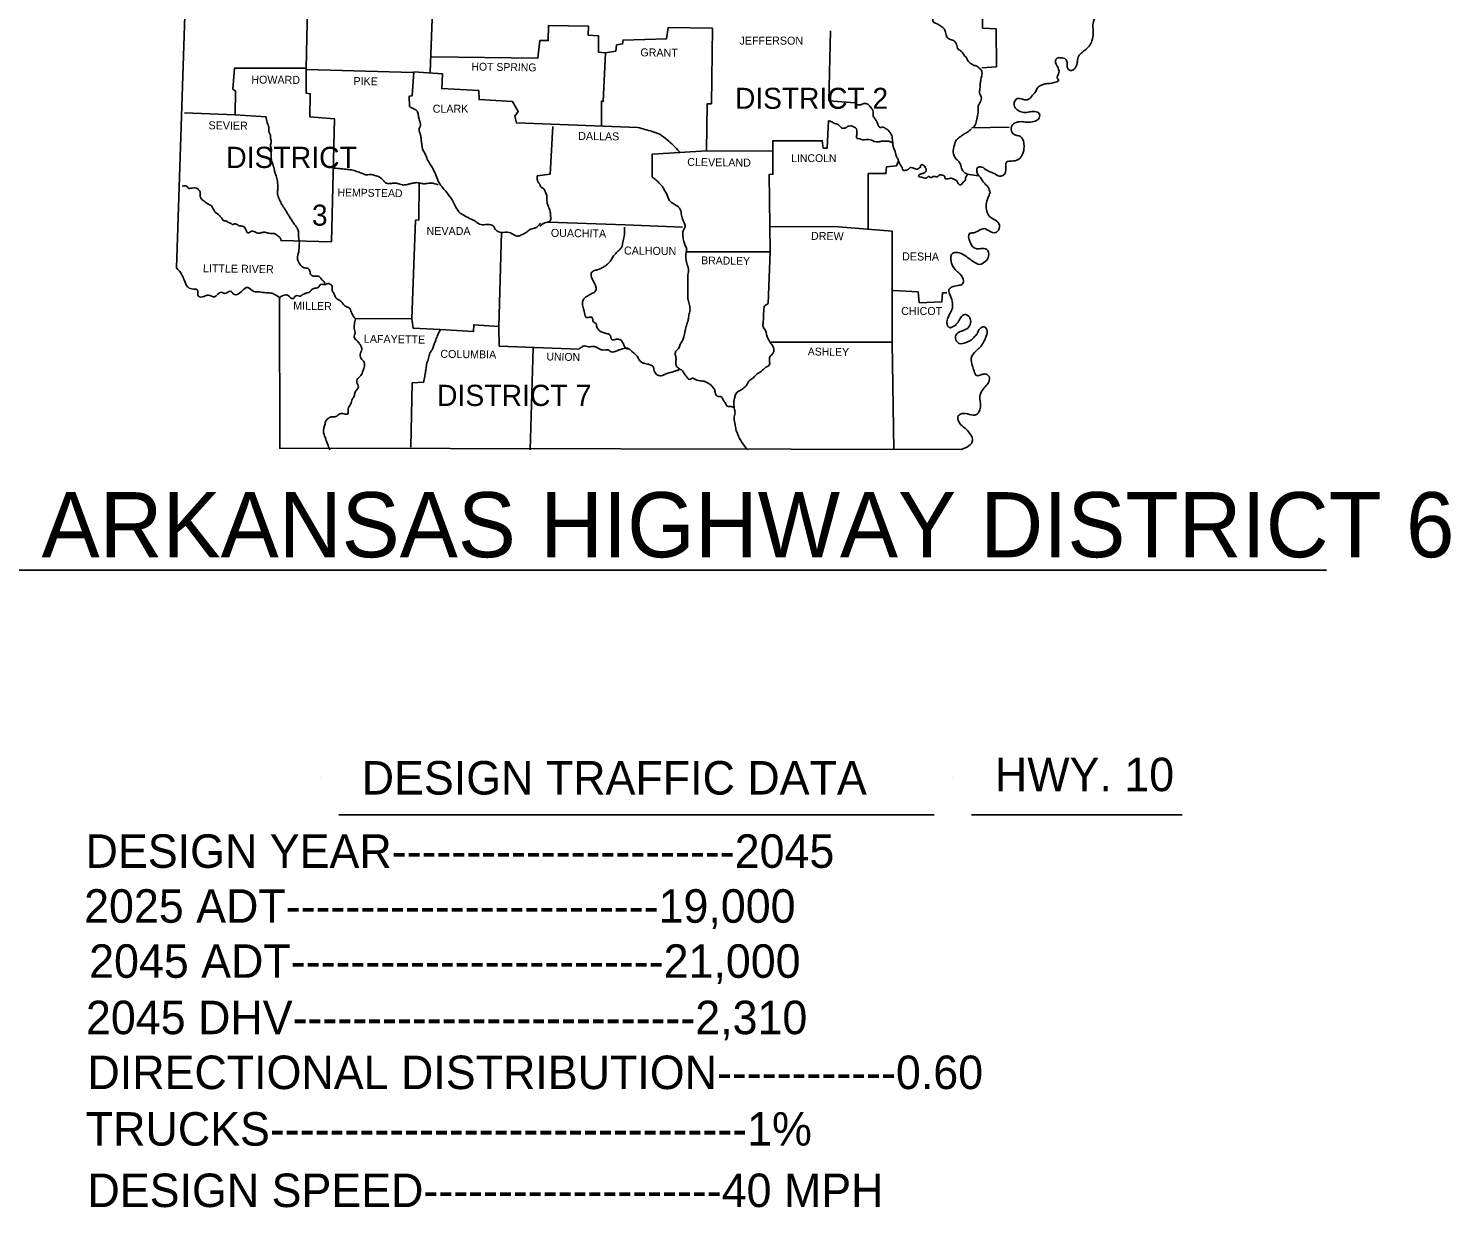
# Model space of a CAD drawing. Extents: x 1096785 to 1382432, y 216169 to 341661.
# Drawn here: x 1204876 to 1220163, y 273845 to 286518 of the extents above; entities that cross this region are included whole.
import ezdxf

# ---------------------------------------------------------------- set-up
doc = ezdxf.new("R2010")
doc.units = 0
for name, color, linetype in [('1', 7, 'Continuous'), ('21', 7, 'Continuous'), ('3', 7, 'Continuous')]:
    doc.layers.add(name, color=color, linetype=linetype)

msp = doc.modelspace()

# ---------------------------------------------------------------- linework, layer by layer
at = {"layer": '1'}
for p, q in [((1215017, 285450), (1215417, 285456)), ((1215089, 284934), (1214963, 284950)), ((1203995, 280696), (1218830, 280696)), ((1208012, 278464), (1208012, 278464)), ((1214812, 278464), (1214812, 278464)), ((1208212, 278064), (1214612, 278064)), ((1215012, 278064), (1217276, 278064))]:
    msp.add_line(p, q, dxfattribs=at)
for points in [[(1206467, 283946), (1206647, 289372), (1206233, 292696)], [(1206553, 285612), (1207099, 285588), (1207101, 285844), (1207073, 285864), (1207091, 286092), (1207861, 286090), (1207883, 287074), (1208019, 287062), (1208021, 287184), (1208161, 287188), (1208159, 287220), (1208253, 287220), (1208255, 287264), (1208351, 287262), (1208343, 287322), (1208443, 287324), (1208446, 288143)], [(1215125, 286096), (1215281, 286106), (1215279, 286512), (1215133, 286522), (1215141, 287316), (1215015, 287334), (1215011, 287868), (1216717, 287880)], [(1209193, 286048), (1209239, 287294)], [(1209207, 286214), (1210351, 286198), (1210373, 286388), (1210463, 286388), (1210465, 286548), (1210897, 286542), (1210893, 286446), (1211005, 286438), (1211005, 286262), (1211077, 286256)], [(1212229, 286520), (1211751, 286528), (1211733, 286406), (1211267, 286392), (1211263, 286352), (1211197, 286340), (1211189, 286272), (1211077, 286256)], [(1212229, 286516), (1212217, 285708), (1212171, 285706), (1212165, 285204)], [(1213497, 286494), (1213481, 285740), (1213759, 285718)], [(1211077, 286256), (1211053, 285732), (1211035, 285738), (1211037, 285466)], [(1207861, 286090), (1207861, 285824), (1207905, 285816), (1207901, 285568), (1208165, 285548), (1208133, 284226), (1207589, 284240)], [(1207865, 286076), (1209009, 286046)], [(1208971, 285680), (1208967, 285790), (1208999, 285792), (1209019, 286050), (1209327, 286030), (1209319, 285872), (1209717, 285850), (1209719, 285754), (1210079, 285732), (1210141, 285624), (1210103, 285576), (1210121, 285502), (1211425, 285454)], [(1207099, 285588), (1207431, 285568)], [(1210513, 285464), (1210483, 284950), (1210345, 284934)], [(1213475, 285526), (1213463, 285232), (1213417, 285232), (1213409, 285310), (1212877, 285310), (1212877, 285198)], [(1211877, 285186), (1211581, 285168), (1211579, 284918)], [(1211873, 285186), (1212165, 285204)], [(1212165, 285204), (1212873, 285200)], [(1212877, 285200), (1212879, 284950), (1212837, 284948), (1212849, 284118)], [(1214229, 285094), (1214205, 285040), (1214099, 285030), (1214093, 284958), (1213903, 284958), (1213901, 284360)], [(1209077, 284858), (1209073, 284460), (1209037, 284456), (1208997, 283402)], [(1210463, 284436), (1211291, 284406), (1211905, 284382)], [(1212843, 284390), (1213585, 284384), (1214161, 284340)], [(1214161, 284340), (1214161, 283144), (1214177, 281994)], [(1209301, 283282), (1209661, 283260), (1209663, 283334), (1209933, 283316), (1209959, 284324)], [(1211945, 284116), (1212849, 284118)], [(1212849, 284118), (1212829, 283562), (1212785, 283534)], [(1214907, 281994), (1207577, 282006), (1207573, 283624)], [(1214171, 283702), (1214439, 283686), (1214451, 283570), (1214693, 283578), (1214703, 283676), (1214749, 283676)], [(1209301, 283282), (1209011, 283298), (1208997, 283402), (1208391, 283396)], [(1210791, 283072), (1209937, 283104), (1209933, 283306)], [(1212849, 283146), (1214161, 283146)], [(1210301, 283086), (1210269, 281988)], [(1208987, 282016), (1209001, 282708), (1209125, 282716)]]:
    msp.add_lwpolyline(points, dxfattribs=at)
for points in [[(1216591, 287396), (1216545, 287338), (1216477, 287374), (1216477, 287422), (1216487, 287472), (1216463, 287504), (1216421, 287490), (1216421, 287428), (1216417, 287368), (1216405, 287282), (1216433, 287256), (1216497, 287248), (1216543, 287236), (1216571, 287190), (1216569, 287134), (1216547, 287080), (1216515, 287036), (1216465, 287020), (1216425, 287046), (1216409, 287098), (1216391, 287144), (1216357, 287178), (1216321, 287140), (1216313, 287070), (1216315, 287010), (1216315, 286928), (1216367, 286874), (1216399, 286812), (1216389, 286756), (1216351, 286690), (1216335, 286632), (1216319, 286554), (1216321, 286468), (1216307, 286384), (1216279, 286328), (1216227, 286282), (1216193, 286252), (1216165, 286222), (1216151, 286162), (1216141, 286120), (1216103, 286070), (1216073, 286066), (1216049, 286086), (1216041, 286120), (1216041, 286154), (1216025, 286188), (1215975, 286202), (1215935, 286200), (1215917, 286172), (1215943, 286094), (1215953, 286044), (1215939, 285976), (1215947, 285968), (1215875, 285930), (1215817, 285924), (1215769, 285910), (1215723, 285880), (1215701, 285836), (1215669, 285800), (1215641, 285766), (1215603, 285750), (1215561, 285758), (1215505, 285764), (1215473, 285724), (1215483, 285666), (1215521, 285632), (1215577, 285616), (1215635, 285620), (1215691, 285626), (1215743, 285598), (1215733, 285544), (1215683, 285518), (1215609, 285510), (1215549, 285516), (1215477, 285500), (1215441, 285454), (1215461, 285384), (1215539, 285356), (1215575, 285290), (1215577, 285228), (1215551, 285146), (1215515, 285108), (1215445, 285092), (1215391, 285082), (1215383, 284990), (1215359, 284944), (1215317, 284930), (1215257, 284960), (1215221, 284974), (1215177, 284994), (1215121, 285028), (1215079, 285022), (1215091, 284934), (1215095, 284930), (1215143, 284864), (1215191, 284812), (1215213, 284750)], [(1216591, 287396), (1216545, 287338), (1216477, 287374), (1216477, 287422), (1216487, 287472), (1216463, 287504), (1216421, 287490), (1216421, 287428), (1216417, 287368), (1216405, 287282), (1216433, 287256), (1216497, 287248), (1216543, 287236), (1216571, 287190), (1216569, 287134), (1216547, 287080), (1216515, 287036), (1216465, 287020), (1216425, 287046), (1216409, 287098), (1216391, 287144), (1216357, 287178), (1216321, 287140), (1216313, 287070), (1216315, 287010), (1216315, 286928), (1216367, 286874), (1216399, 286812), (1216389, 286756), (1216351, 286690), (1216335, 286632), (1216319, 286554), (1216321, 286468), (1216307, 286384), (1216279, 286328), (1216227, 286282), (1216193, 286252), (1216165, 286222), (1216151, 286162), (1216141, 286120), (1216103, 286070), (1216073, 286066), (1216049, 286086), (1216041, 286120), (1216041, 286154), (1216025, 286188), (1215975, 286202), (1215935, 286200), (1215917, 286172), (1215943, 286094), (1215953, 286044), (1215939, 285976), (1215947, 285968), (1215875, 285930), (1215817, 285924), (1215769, 285910), (1215723, 285880), (1215701, 285836), (1215669, 285800), (1215641, 285766), (1215603, 285750), (1215561, 285758), (1215505, 285764), (1215473, 285724), (1215483, 285666), (1215521, 285632), (1215577, 285616), (1215635, 285620), (1215691, 285626), (1215743, 285598), (1215733, 285544), (1215683, 285518), (1215609, 285510), (1215549, 285516), (1215477, 285500), (1215441, 285454), (1215461, 285384), (1215539, 285356), (1215575, 285290), (1215577, 285228), (1215551, 285146), (1215515, 285108), (1215445, 285092), (1215391, 285082), (1215383, 284990), (1215359, 284944), (1215317, 284930), (1215257, 284960), (1215221, 284974), (1215177, 284994), (1215121, 285028), (1215079, 285022), (1215091, 284934), (1215095, 284930), (1215143, 284864), (1215191, 284812), (1215213, 284750)], [(1215027, 285450), (1215053, 285482), (1215071, 285544), (1215079, 285582), (1215085, 285648), (1215087, 285692), (1215107, 285724), (1215117, 285784), (1215099, 285824), (1215103, 285872), (1215107, 285926), (1215115, 285974), (1215125, 286020), (1215125, 286050), (1215099, 286090), (1215059, 286116), (1215027, 286126), (1215007, 286140), (1214979, 286164), (1214951, 286212), (1214935, 286230), (1214903, 286272), (1214871, 286296), (1214851, 286350), (1214819, 286388), (1214775, 286404), (1214743, 286438), (1214731, 286490), (1214711, 286522), (1214683, 286542), (1214637, 286570), (1214603, 286590), (1214593, 286636), (1214573, 286658), (1214525, 286670), (1214519, 286752)], [(1213759, 285718), (1213789, 285698), (1213831, 285700), (1213859, 285712), (1213881, 285710), (1213911, 285692), (1213931, 285668), (1213945, 285650), (1213955, 285622), (1213955, 285596), (1213965, 285560), (1213977, 285546), (1213993, 285520), (1214003, 285496), (1214009, 285480), (1214031, 285454), (1214051, 285456), (1214069, 285454), (1214093, 285440), (1214129, 285412), (1214135, 285404), (1214159, 285352), (1214163, 285320), (1214167, 285278), (1214175, 285238), (1214191, 285194), (1214199, 285164), (1214217, 285122), (1214229, 285094), (1214245, 285058), (1214269, 285018), (1214279, 284994), (1214313, 284996), (1214337, 285006), (1214355, 285022), (1214377, 285020), (1214401, 285012), (1214433, 285006), (1214453, 285018), (1214463, 285026), (1214465, 285044), (1214483, 285054), (1214503, 285040), (1214525, 285008), (1214525, 284988), (1214517, 284976), (1214491, 284960), (1214455, 284948), (1214445, 284934), (1214479, 284918), (1214533, 284914), (1214547, 284926), (1214583, 284916), (1214597, 284926), (1214645, 284924), (1214667, 284940), (1214711, 284938), (1214725, 284928), (1214725, 284910), (1214761, 284902), (1214787, 284908), (1214821, 284898), (1214851, 284882), (1214867, 284860), (1214887, 284836), (1214905, 284842), (1214919, 284860), (1214949, 284892), (1214949, 284912), (1214957, 284926), (1214967, 284946)], [(1207431, 285568), (1207441, 285508), (1207459, 285456), (1207461, 285416), (1207479, 285356), (1207479, 285334), (1207485, 285290), (1207477, 285266), (1207487, 285218), (1207485, 285182), (1207485, 285152), (1207487, 285102), (1207503, 285058), (1207519, 284992), (1207529, 284958), (1207545, 284906), (1207555, 284842), (1207557, 284794), (1207553, 284750), (1207565, 284700), (1207587, 284650), (1207615, 284602), (1207649, 284548), (1207673, 284506), (1207703, 284460), (1207727, 284422), (1207763, 284374), (1207779, 284334), (1207779, 284278), (1207787, 284226), (1207785, 284168), (1207781, 284116), (1207767, 284044), (1207777, 284010), (1207815, 283960), (1207839, 283946), (1207881, 283938), (1207901, 283910), (1207913, 283868), (1207955, 283854), (1208001, 283850), (1208023, 283826), (1208053, 283794), (1208063, 283778)], [(1209959, 284324), (1209931, 284332), (1209895, 284356), (1209875, 284392), (1209833, 284410), (1209787, 284410), (1209725, 284414), (1209677, 284448), (1209635, 284468), (1209569, 284502), (1209517, 284534), (1209471, 284598), (1209441, 284656), (1209387, 284734), (1209327, 284810), (1209289, 284860), (1209259, 284934), (1209243, 284970), (1209209, 285038), (1209169, 285100), (1209145, 285158), (1209119, 285206), (1209103, 285276), (1209097, 285328), (1209091, 285372), (1209075, 285436), (1209087, 285464), (1209083, 285516), (1209069, 285566), (1209061, 285612), (1209041, 285642), (1209003, 285660), (1208971, 285680)], [(1211425, 285454), (1211581, 285410), (1211661, 285380), (1211741, 285322), (1211807, 285264), (1211873, 285190)], [(1213475, 285526), (1213511, 285514), (1213537, 285500), (1213571, 285488), (1213593, 285472), (1213623, 285446), (1213659, 285450), (1213685, 285466), (1213711, 285470), (1213731, 285468), (1213753, 285456), (1213777, 285438), (1213781, 285412), (1213781, 285382), (1213781, 285340), (1213795, 285334), (1213845, 285322), (1213879, 285324), (1213911, 285324), (1213937, 285318), (1213959, 285306), (1213975, 285302), (1213999, 285298), (1214019, 285300), (1214053, 285308), (1214073, 285308), (1214105, 285308), (1214125, 285306), (1214155, 285290)], [(1214969, 284952), (1214955, 284958), (1214911, 285000), (1214893, 285060), (1214869, 285094), (1214833, 285136), (1214817, 285184), (1214829, 285264), (1214851, 285322), (1214897, 285356), (1214935, 285384), (1214971, 285404), (1215013, 285438)], [(1208161, 285016), (1208237, 285010), (1208307, 285002), (1208361, 284996), (1208417, 284976), (1208467, 284958), (1208499, 284944), (1208553, 284948), (1208599, 284938), (1208651, 284920), (1208689, 284886), (1208713, 284860), (1208759, 284850), (1208797, 284856), (1208843, 284852), (1208895, 284836), (1208937, 284838), (1208971, 284846), (1209011, 284856), (1209061, 284860), (1209099, 284852), (1209149, 284850), (1209207, 284856), (1209279, 284836)], [(1206529, 284822), (1206573, 284824), (1206603, 284798), (1206621, 284800), (1206653, 284804), (1206683, 284802), (1206705, 284784), (1206723, 284752), (1206721, 284722), (1206723, 284710), (1206737, 284684), (1206761, 284664), (1206787, 284644), (1206811, 284628), (1206851, 284602), (1206855, 284594), (1206871, 284562), (1206891, 284536), (1206915, 284520), (1206941, 284492), (1206953, 284480), (1206973, 284452), (1206995, 284450), (1207025, 284432), (1207047, 284426), (1207071, 284410), (1207095, 284418), (1207125, 284406), (1207165, 284394), (1207187, 284390), (1207213, 284352), (1207239, 284320), (1207271, 284338), (1207331, 284320), (1207369, 284318), (1207403, 284328), (1207429, 284326), (1207477, 284314), (1207507, 284314), (1207539, 284302), (1207569, 284278), (1207589, 284252), (1207589, 284240)], [(1210345, 284934), (1210345, 284896), (1210359, 284860), (1210373, 284844), (1210379, 284818), (1210397, 284806), (1210423, 284782), (1210437, 284748), (1210447, 284726), (1210447, 284698), (1210449, 284670), (1210453, 284636), (1210477, 284576), (1210483, 284552), (1210487, 284532), (1210489, 284498), (1210489, 284458), (1210463, 284436)], [(1211579, 284918), (1211625, 284888), (1211663, 284848), (1211691, 284818), (1211709, 284784), (1211733, 284744), (1211767, 284668), (1211797, 284642), (1211839, 284616), (1211865, 284598), (1211891, 284540), (1211903, 284482), (1211925, 284430), (1211935, 284390), (1211917, 284350), (1211913, 284270), (1211925, 284216), (1211941, 284176), (1211951, 284130), (1211945, 284116)], [(1215213, 284750), (1215193, 284704), (1215171, 284624), (1215177, 284556), (1215207, 284498), (1215255, 284466), (1215307, 284420), (1215303, 284350), (1215273, 284324), (1215203, 284342), (1215149, 284366), (1215103, 284352), (1215041, 284322), (1214995, 284316), (1214997, 284220), (1215059, 284152), (1215113, 284152), (1215175, 284144), (1215197, 284072), (1215161, 284012), (1215101, 283982), (1215025, 284018), (1214971, 284056), (1214917, 284092), (1214849, 284110), (1214811, 284102), (1214793, 284018), (1214825, 283942), (1214877, 283890), (1214925, 283822), (1214917, 283772), (1214881, 283758), (1214817, 283744), (1214779, 283724), (1214769, 283708), (1214789, 283640), (1214807, 283566), (1214807, 283510), (1214785, 283458), (1214751, 283378), (1214755, 283326), (1214779, 283302), (1214809, 283310), (1214849, 283338), (1214875, 283370), (1214897, 283410), (1214939, 283444), (1214991, 283414), (1215003, 283352), (1214973, 283298), (1214931, 283274), (1214879, 283254), (1214841, 283210), (1214851, 283158), (1214881, 283130), (1214955, 283144), (1215005, 283166), (1215033, 283194), (1215067, 283228), (1215085, 283262), (1215111, 283298), (1215157, 283308), (1215179, 283278), (1215171, 283210), (1215143, 283146), (1215105, 283092), (1215063, 283054), (1215011, 282972), (1215021, 282896), (1215041, 282834), (1215069, 282786), (1215117, 282796), (1215171, 282802), (1215203, 282776), (1215199, 282720), (1215159, 282666), (1215121, 282614), (1215101, 282542), (1215109, 282492), (1215109, 282446), (1215093, 282396), (1215065, 282368), (1214991, 282370), (1214913, 282378), (1214871, 282354), (1214879, 282286), (1214925, 282236), (1214957, 282210), (1215003, 282154), (1215023, 282108), (1215017, 282068), (1214989, 282034), (1214907, 281994)], [(1215213, 284750), (1215193, 284704), (1215171, 284624), (1215177, 284556), (1215207, 284498), (1215255, 284466), (1215307, 284420), (1215303, 284350), (1215273, 284324), (1215203, 284342), (1215149, 284366), (1215103, 284352), (1215041, 284322), (1214995, 284316), (1214997, 284220), (1215059, 284152), (1215113, 284152), (1215175, 284144), (1215197, 284072), (1215161, 284012), (1215101, 283982), (1215025, 284018), (1214971, 284056), (1214917, 284092), (1214849, 284110), (1214811, 284102), (1214793, 284018), (1214825, 283942), (1214877, 283890), (1214925, 283822), (1214917, 283772), (1214881, 283758), (1214817, 283744), (1214779, 283724), (1214769, 283708), (1214789, 283640), (1214807, 283566), (1214807, 283510), (1214785, 283458), (1214751, 283378), (1214755, 283326), (1214779, 283302), (1214809, 283310), (1214849, 283338), (1214875, 283370), (1214897, 283410), (1214939, 283444), (1214991, 283414), (1215003, 283352), (1214973, 283298), (1214931, 283274), (1214879, 283254), (1214841, 283210), (1214851, 283158), (1214881, 283130), (1214955, 283144), (1215005, 283166), (1215033, 283194), (1215067, 283228), (1215085, 283262), (1215111, 283298), (1215157, 283308), (1215179, 283278), (1215171, 283210), (1215143, 283146), (1215105, 283092), (1215063, 283054), (1215011, 282972), (1215021, 282896), (1215041, 282834), (1215069, 282786), (1215117, 282796), (1215171, 282802), (1215203, 282776), (1215199, 282720), (1215159, 282666), (1215121, 282614), (1215101, 282542), (1215109, 282492), (1215109, 282446), (1215093, 282396), (1215065, 282368), (1214991, 282370), (1214913, 282378), (1214871, 282354), (1214879, 282286), (1214925, 282236), (1214957, 282210), (1215003, 282154), (1215023, 282108), (1215017, 282068), (1214989, 282034), (1214907, 281994)], [(1210381, 284426), (1210359, 284400), (1210333, 284378), (1210303, 284368), (1210275, 284360), (1210239, 284336), (1210211, 284316), (1210173, 284298), (1210137, 284286), (1210093, 284300), (1210069, 284314), (1210043, 284324), (1209959, 284324)], [(1210373, 284394), (1210425, 284428), (1210483, 284436)], [(1211283, 284382), (1211279, 284282), (1211265, 284220), (1211251, 284164), (1211221, 284132), (1211189, 284100), (1211159, 284064), (1211133, 284020), (1211107, 283992), (1211073, 283964), (1211039, 283944), (1211001, 283926), (1210959, 283916), (1210929, 283894), (1210927, 283846), (1210961, 283778), (1210973, 283746), (1210977, 283708), (1210963, 283686), (1210931, 283668), (1210893, 283646), (1210859, 283626), (1210835, 283592), (1210831, 283546), (1210847, 283492), (1210853, 283460), (1210879, 283410), (1210899, 283412), (1210935, 283410), (1210939, 283400), (1210941, 283390), (1210949, 283364), (1210979, 283342), (1210983, 283322), (1211001, 283284), (1211031, 283258), (1211053, 283250), (1211099, 283236), (1211123, 283230), (1211149, 283172), (1211181, 283174), (1211205, 283178), (1211245, 283168), (1211263, 283144), (1211281, 283104), (1211305, 283076), (1211321, 283076)], [(1211945, 284116), (1211953, 283992), (1211971, 283932), (1211965, 283868), (1211963, 283806), (1211963, 283750), (1211963, 283696), (1211963, 283640), (1211967, 283600), (1211981, 283542), (1211987, 283488), (1211975, 283436), (1211969, 283388), (1211953, 283340), (1211939, 283286), (1211923, 283216), (1211909, 283170), (1211881, 283122), (1211863, 283078), (1211835, 283050), (1211831, 283002), (1211837, 282958), (1211833, 282918), (1211847, 282880), (1211883, 282854)], [(1207573, 283624), (1207581, 283620), (1207543, 283646), (1207491, 283672), (1207433, 283676), (1207359, 283686), (1207297, 283692), (1207233, 283734), (1207165, 283690), (1207089, 283658), (1207045, 283694), (1206987, 283670), (1206947, 283682), (1206877, 283634), (1206811, 283652), (1206763, 283638), (1206703, 283640), (1206691, 283708), (1206633, 283718), (1206583, 283746), (1206549, 283816), (1206525, 283870), (1206467, 283946)], [(1207573, 283624), (1207643, 283654), (1207673, 283644), (1207699, 283618), (1207729, 283618), (1207745, 283642), (1207775, 283644), (1207799, 283642), (1207825, 283658), (1207847, 283668), (1207877, 283678), (1207899, 283686), (1207919, 283708), (1207955, 283726), (1207997, 283740), (1208009, 283760), (1208029, 283768), (1208069, 283766), (1208095, 283778), (1208117, 283768), (1208137, 283754), (1208141, 283702), (1208157, 283674), (1208181, 283624), (1208215, 283598), (1208247, 283572), (1208259, 283556), (1208293, 283526), (1208323, 283516), (1208337, 283494), (1208359, 283442), (1208391, 283396)], [(1212785, 283534), (1212779, 283472), (1212777, 283414), (1212773, 283358), (1212773, 283316), (1212797, 283270), (1212811, 283226), (1212825, 283188), (1212853, 283138), (1212879, 283100), (1212887, 283046), (1212871, 283018), (1212841, 282976), (1212839, 282900), (1212803, 282876), (1212757, 282836), (1212731, 282818), (1212703, 282800), (1212673, 282768), (1212629, 282738), (1212597, 282688), (1212561, 282650), (1212531, 282630), (1212489, 282604), (1212471, 282564), (1212457, 282490), (1212463, 282436), (1212471, 282388), (1212461, 282328), (1212471, 282262), (1212481, 282210), (1212497, 282164), (1212519, 282112), (1212547, 282064), (1212607, 281990)], [(1208391, 283396), (1208379, 283338), (1208377, 283292), (1208387, 283238), (1208377, 283212), (1208393, 283174), (1208423, 283144), (1208445, 283112), (1208459, 283066), (1208441, 283014), (1208461, 282960), (1208479, 282940), (1208489, 282908), (1208475, 282846), (1208457, 282800), (1208417, 282754), (1208405, 282732), (1208411, 282702), (1208421, 282654), (1208411, 282640), (1208385, 282606), (1208377, 282568), (1208359, 282536), (1208339, 282478), (1208313, 282430), (1208309, 282376), (1208269, 282376), (1208223, 282376), (1208181, 282346), (1208143, 282344), (1208097, 282326), (1208069, 282288), (1208059, 282246), (1208047, 282206), (1208059, 282138), (1208077, 282090), (1208091, 282052), (1208115, 281990)], [(1209125, 282716), (1209135, 282780), (1209145, 282830), (1209151, 282878), (1209163, 282932), (1209181, 282990), (1209197, 283038), (1209219, 283072), (1209233, 283112), (1209251, 283160), (1209269, 283210), (1209301, 283274)], [(1210791, 283072), (1210823, 283094), (1210853, 283106), (1210883, 283100), (1210915, 283096), (1210943, 283100), (1210979, 283094), (1211009, 283076), (1211043, 283062), (1211077, 283062), (1211107, 283062), (1211133, 283044), (1211181, 283046), (1211221, 283062), (1211261, 283074), (1211315, 283080), (1211363, 283046), (1211397, 283018), (1211425, 282986), (1211445, 282950), (1211467, 282930), (1211503, 282916), (1211531, 282910), (1211565, 282900), (1211583, 282892), (1211599, 282854), (1211625, 282802), (1211675, 282784), (1211737, 282808), (1211787, 282822), (1211823, 282834), (1211845, 282842), (1211865, 282844), (1211859, 282848), (1211883, 282854), (1211905, 282838), (1211919, 282816), (1211943, 282784), (1211965, 282756), (1211987, 282746), (1212009, 282758), (1212039, 282748), (1212065, 282738), (1212095, 282730), (1212121, 282728), (1212155, 282720), (1212181, 282706), (1212205, 282692), (1212229, 282666), (1212253, 282626), (1212261, 282594), (1212289, 282562), (1212315, 282562), (1212353, 282510), (1212367, 282490), (1212397, 282454), (1212419, 282454), (1212461, 282446)]]:
    msp.add_spline(points, degree=3, dxfattribs=at)

# ---------------------------------------------------------------- texts
for s, p in [('HWY. 10', (1215265, 278320)), ('DESIGN TRAFFIC DATA', (1208458, 278284))]:
    msp.add_text(s, height=360, dxfattribs=at).set_placement(p)
at = {"layer": '21'}
msp.add_text('PIKE', height=86, rotation=359.0452, dxfattribs=at).set_placement((1208369, 285910))
for s, height, p in [('DISTRICT 2', 226, (1212471, 285654)), ('DISTRICT', 228, (1207001, 285018)), ('3', 226, (1207923, 284398)), ('DISTRICT 7', 228, (1209267, 282460))]:
    msp.add_text(s, height=height, dxfattribs=at).set_placement(p)
at = {"layer": '3'}
for s, height, p in [('JEFFERSON', 86, (1212519, 286344)), ('CLARK', 86, (1209221, 285612)), ('LINCOLN', 84, (1213075, 285082)), ('NEVADA', 86, (1209155, 284298)), ('CHICOT', 86, (1214257, 283438)), ('ARKANSAS HIGHWAY DISTRICT 6', 700, (1205017, 280834)), ('DESIGN YEAR-----------------------2045', 360, (1205490, 277496)), ('2025 ADT-------------------------19,000', 360, (1205474, 276906)), ('2045 ADT-------------------------21,000', 360, (1205528, 276314)), ('2045 DHV---------------------------2,310', 360, (1205494, 275708)), ('DIRECTIONAL DISTRIBUTION------------0.60', 360, (1205510, 275118)), ('TRUCKS--------------------------------1%', 360, (1205492, 274510)), ('DESIGN SPEED--------------------40 MPH', 360, (1205510, 273850))]:
    msp.add_text(s, height=height, dxfattribs=at).set_placement(p)
for s, height, rotation, p in [('GRANT', 86, 359.4032, (1211453, 286218)), ('HOT SPRING', 84, 359.2216, (1209637, 286066)), ('HOWARD', 86, 359.5145, (1207271, 285926)), ('SEVIER', 86, 359.4271, (1206811, 285434)), ('DALLAS', 86, 359.2462, (1210785, 285320)), ('CLEVELAND', 86, 359.3376, (1211957, 285040)), ('HEMPSTEAD', 84, 359.1885, (1208197, 284714)), ('OUACHITA', 86, 359.2043, (1210491, 284278)), ('DREW', 86, 359.2258, (1213287, 284246)), ('CALHOUN', 86, 359.3634, (1211277, 284088)), ('BRADLEY', 84, 359.1449, (1212107, 283984)), ('DESHA', 86, 359.3704, (1214267, 284026)), ('LITTLE RIVER', 86.02, 359.1697, (1206751, 283898)), ('MILLER', 86, 359.1319, (1207721, 283496)), ('LAFAYETTE', 86, 359.1839, (1208481, 283140)), ('COLUMBIA', 86, 359.2125, (1209303, 282978)), ('UNION', 84, 358.9584, (1210443, 282950)), ('ASHLEY', 84, 359.2361, (1213253, 283004))]:
    msp.add_text(s, height=height, rotation=rotation, dxfattribs=at).set_placement(p)

doc.saveas('drawing.dxf')
